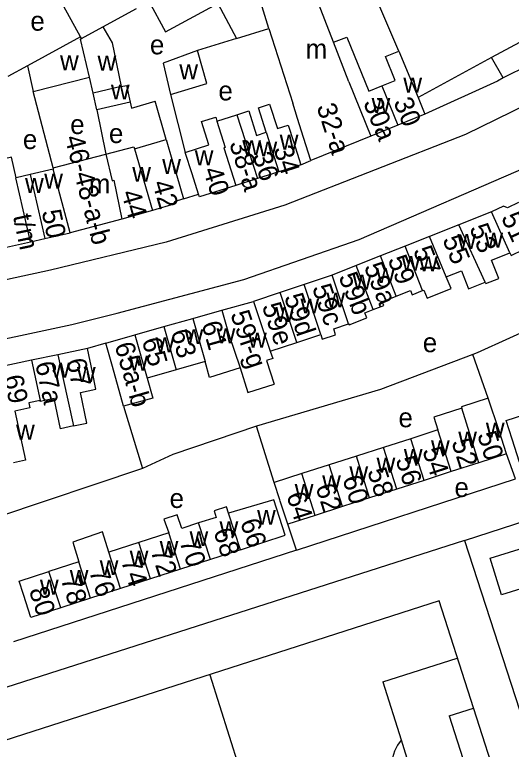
# Model space of a CAD drawing. Extents: x 157569 to 159501, y 382907 to 384670.
# Drawn here: x 159134.2 to 159236.8, y 383198.5 to 383350.2 of the extents above; entities that cross this region are included whole.
import ezdxf

# ---------------------------------------------------------------- set-up
doc = ezdxf.new("R2010")
doc.units = 0
for name, color, linetype in [('BLT_Basislijn', 7, 'Continuous'), ('BLT_Bebouwing', 7, 'Continuous'), ('BLT_Centroide', 7, 'Continuous'), ('BLT_Huisnummer', 7, 'Continuous'), ('BLT_Huisnummer_ tussenligend', 7, 'Continuous'), ('BLT_Huisnummer_reeks', 7, 'Continuous'), ('BLT_Onderdoorgang_en_onderverdeling', 7, 'Continuous'), ('BLT_Onderverdeling_panden', 7, 'Continuous')]:
    doc.layers.add(name, color=color, linetype=linetype)

msp = doc.modelspace()

# ---------------------------------------------------------------- linework, layer by layer
at = {"layer": 'BLT_Basislijn'}
for p, q in [((159262.09, 383350.88), (159235.12, 383337.11)), ((159180, 383345.26), (159171.98, 383342.81)), ((159235.12, 383337.11), (159232.71, 383341.31)), ((159136.86, 383339.6), (159132.8, 383337.38)), ((159166.38, 383333.67), (159169.45, 383321.74)), ((159165.51, 383324.4), (159163.22, 383332.29)), ((159151.19, 383330.54), (159153.01, 383321.36)), ((159193.32, 383319.19), (159195.37, 383320.06)), ((159169.08, 383312.13), (159172.19, 383313.1)), ((159153.02, 383282.36), (159149.23, 383281.25)), ((159232, 383270.96), (159228.83, 383279.98)), ((159156.72, 383269.31), (159160.58, 383256.46)), ((159187.8, 383253.56), (159184.15, 383265.21)), ((159237.62, 383254.3), (159235.8, 383259.46)), ((159160.58, 383256.46), (159126.18, 383244.9)), ((159192.4, 383239.63), (159237.62, 383254.3)), ((159192.4, 383239.63), (159190.6, 383244.94)), ((159227.11, 383241.57), (159118.79, 383206.87)), ((159192.4, 383239.63), (159133.97, 383220.64)), ((159210.21, 383212.39), (159225.62, 383217.27)), ((159174.52, 383213.85), (159181.45, 383191.99)), ((159210.21, 383212.39), (159214.01, 383200.41)), ((159223.95, 383205.38), (159228.94, 383206.96)), ((159223.95, 383205.38), (159228.04, 383192.5)), ((159214.01, 383200.4), (159222.38, 383174))]:
    msp.add_line(p, q, dxfattribs=at)
for points in [[(158983.24, 383235.61), (158982.98, 383236.31), (158981.28, 383239.26), (158981.31, 383241.77), (158983.04, 383243.59), (159007.41, 383254.28), (159036.07, 383262.73), (159100, 383276.35), (159146.03, 383286.21), (159155.39, 383288.52), (159181.52, 383295.52), (159205.36, 383303.77), (159241.92, 383319.57), (159301.34, 383349.43)], [(159258.99, 383340.92), (159227.33, 383325.46), (159190.02, 383310.81), (159165.47, 383303.18), (159141.61, 383297.45), (159119.64, 383292.64), (159100, 383288.81), (159051.92, 383279.92), (159027.35, 383274.07), (158997.57, 383264.08), (158986.46, 383259.17)], [(159235.12, 383337.11), (159233.89, 383336.44), (159218.91, 383329.63)], [(159142.14, 383318.53), (159138.07, 383334.3)], [(159158.09, 383332.11), (159158.37, 383330.89), (159163.22, 383332.29)], [(159243.1, 383286.39), (159229.71, 383280.36), (159228.83, 383279.98)], [(159228.83, 383279.98), (159209.75, 383272.75), (159184.15, 383265.21)], [(159227.11, 383241.57), (159314.29, 383269.88), (159323.12, 383265.83)], [(159184.15, 383265.21), (159166.87, 383259.35), (159160.58, 383256.46)], [(159227.11, 383241.57), (159242, 383195.83)], [(159214, 383200.39), (159213.28, 383199.32), (159212.68, 383198.1), (159212.23, 383196.73), (159211.98, 383195.26), (159211.96, 383193.71), (159212.19, 383192.15), (159212.67, 383190.64), (159213.38, 383189.23), (159214.29, 383187.98), (159215.35, 383186.92), (159216.5, 383186.06), (159217.7, 383185.41), (159218.9, 383184.96)]]:
    msp.add_lwpolyline(points, dxfattribs=at)
msp.add_lwpolyline([(159221.86, 383229.13), (159126.16, 383198.35), (159145.8, 383137.26), (159241.51, 383168.04)], close=True, dxfattribs=at)
at = {"layer": 'BLT_Bebouwing'}
for p, q in [((159213.51, 383342.64), (159200.32, 383373.83)), ((159200.04, 383344.48), (159190.74, 383368.68)), ((159255.71, 383353.81), (159232.71, 383341.31)), ((159152.4, 383347.65), (159159.35, 383351.46)), ((159180, 383345.26), (159186.71, 383347.31)), ((159186.71, 383347.31), (159191.64, 383331.91)), ((159147.8, 383345.57), (159136.86, 383339.6)), ((159171.98, 383342.81), (159164.85, 383340.15)), ((159173.93, 383335.93), (159171.98, 383342.81)), ((159164.85, 383340.15), (159166.38, 383333.67)), ((159232.71, 383341.31), (159217.54, 383333.06)), ((159136.86, 383339.6), (159138.07, 383334.3)), ((159138.07, 383334.3), (159149.65, 383337.3)), ((159150.4, 383333.99), (159149.65, 383337.3)), ((159156.2, 383335.32), (159157.31, 383335.57)), ((159157.31, 383335.57), (159158.09, 383332.11)), ((159166.38, 383333.67), (159173.93, 383335.93)), ((159151.19, 383330.54), (159150.4, 383333.99)), ((159217.54, 383333.06), (159218.91, 383329.63)), ((159158.09, 383332.11), (159151.19, 383330.54)), ((159175.99, 383328.2), (159180.08, 383329.5)), ((159218.91, 383329.63), (159213.36, 383327.37)), ((159213.36, 383327.37), (159207.78, 383325.11)), ((159207.78, 383325.11), (159195.37, 383320.06)), ((159142.14, 383318.53), (159153.01, 383321.36)), ((159193.32, 383319.19), (159188.76, 383317.74)), ((159142.14, 383318.53), (159142.2, 383318.27)), ((159188.76, 383317.74), (159184.34, 383316.34)), ((159184.34, 383316.34), (159179.89, 383314.93)), ((159162.65, 383309.77), (159156.34, 383307.94)), ((159232.66, 383309.45), (159225.95, 383306.79)), ((159225.95, 383306.79), (159219.9, 383304.39)), ((159137.5, 383303.29), (159140.46, 383303.97)), ((159140.46, 383303.97), (159145.65, 383305.16)), ((159219.9, 383304.39), (159214.84, 383302.38)), ((159128.14, 383301.18), (159137.5, 383303.29)), ((159214.84, 383302.38), (159209.79, 383300.37)), ((159209.79, 383300.37), (159204.71, 383298.36)), ((159204.71, 383298.36), (159199.79, 383296.4)), ((159199.79, 383296.4), (159193.98, 383294.46)), ((159193.98, 383294.46), (159189.05, 383292.81)), ((159189.05, 383292.81), (159183.55, 383290.97)), ((159177.03, 383289.17), (159183.55, 383290.97)), ((159171.03, 383287.47), (159177.03, 383289.17)), ((159165.03, 383285.77), (159171.03, 383287.47)), ((159159.03, 383284.07), (159165.03, 383285.77)), ((159153.02, 383282.36), (159159.03, 383284.07)), ((159187, 383280.68), (159192.49, 383282.51)), ((159149.23, 383281.25), (159143.13, 383279.96)), ((159143.13, 383279.96), (159137.71, 383278.81)), ((159137.71, 383278.81), (159129.52, 383277.08)), ((159173.56, 383278.55), (159167.56, 383276.85)), ((159167.56, 383276.85), (159161.55, 383275.15)), ((159221.62, 383264.42), (159216, 383262.61)), ((159216, 383262.61), (159210.39, 383260.81)), ((159210.39, 383260.81), (159204.77, 383259.01)), ((159204.77, 383259.01), (159199.15, 383257.21)), ((159235.8, 383259.46), (159230.08, 383257.62)), ((159199.15, 383257.21), (159193.53, 383255.4)), ((159230.08, 383257.62), (159224.38, 383255.81)), ((159193.53, 383255.4), (159187.8, 383253.56)), ((159224.38, 383255.81), (159218.76, 383254.01)), ((159218.76, 383254.01), (159213.14, 383252.22)), ((159213.14, 383252.22), (159207.52, 383250.42)), ((159201.91, 383248.61), (159196.3, 383246.79)), ((159196.3, 383246.79), (159190.6, 383244.94)), ((159166.03, 383243.2), (159159.84, 383241.2)), ((159159.84, 383241.2), (159153.66, 383239.2)), ((159180.83, 383239.7), (159174.64, 383237.7)), ((159147.48, 383237.19), (159141.29, 383235.19)), ((159174.64, 383237.7), (159168.46, 383235.69)), ((159168.46, 383235.69), (159162.27, 383233.69)), ((159162.27, 383233.69), (159156.09, 383231.69)), ((159156.09, 383231.69), (159149.91, 383229.68)), ((159149.91, 383229.68), (159143.73, 383227.68))]:
    msp.add_line(p, q, dxfattribs=at)
for points in [[(159147.8, 383345.57), (159131.42, 383375.48), (159129.2, 383379.53)], [(159161.82, 383353.07), (159165.38, 383346.61), (159176.15, 383352.51), (159180, 383345.26)], [(159152.4, 383347.65), (159154.32, 383344.35), (159156.2, 383335.32)], [(159200.04, 383344.48), (159202.79, 383345.53), (159207.32, 383334.38), (159210.06, 383335.49)], [(159210.06, 383335.49), (159212.79, 383336.6), (159210.79, 383341.53), (159213.51, 383342.64)], [(159186.18, 383325.88), (159184.57, 383330.95), (159186.87, 383331.68), (159188.46, 383326.66), (159190.71, 383327.39), (159191.81, 383323.96), (159193.32, 383319.19)], [(159195.37, 383320.06), (159193.85, 383324.83), (159192.6, 383328.76), (159191.64, 383331.91)], [(159180.08, 383329.5), (159182.56, 383330.29), (159184.16, 383325.24), (159186.18, 383325.88)], [(159169.45, 383321.74), (159174.34, 383323.29), (159172.82, 383328.09), (159175.75, 383329.03), (159175.99, 383328.2)], [(159158.95, 383322.49), (159162.5, 383323.52), (159165.51, 383324.4)], [(159165.51, 383324.4), (159166.83, 383319.88), (159167.69, 383316.93), (159169.08, 383312.13)], [(159153.01, 383321.36), (159158.84, 383322.89), (159158.95, 383322.49)], [(159134.54, 383316.5), (159133.56, 383320.73), (159130.86, 383320.12), (159131.82, 383315.88), (159125.38, 383314.4)], [(159172.19, 383313.1), (159170.85, 383317.31), (159169.45, 383321.74)], [(159142.2, 383318.27), (159137.41, 383317.16)], [(159145.65, 383305.16), (159142.2, 383318.27)], [(159137.41, 383317.16), (159134.54, 383316.5)], [(159179.89, 383314.93), (159172.37, 383312.55), (159172.19, 383313.1)], [(159169.08, 383312.13), (159167.14, 383311.56), (159167.27, 383311.11), (159162.65, 383309.77)], [(159238.23, 383311.37), (159236.01, 383310.32), (159235.14, 383310.63), (159232.66, 383309.45)], [(159156.34, 383307.94), (159145.65, 383305.16)], [(159231.39, 383294.93), (159231.53, 383294.63), (159234.2, 383295.7), (159232.69, 383299.47), (159234.59, 383300.23), (159236.49, 383300.99)], [(159236.49, 383300.99), (159236.74, 383300.44), (159239.27, 383301.68), (159240.47, 383299.26), (159243.32, 383300.66)], [(159223.33, 383296.04), (159226.45, 383297.28), (159227.94, 383293.55), (159231.39, 383294.93)], [(159218.42, 383293.19), (159218.71, 383293.3), (159219.38, 383291.63), (159224.33, 383293.6), (159223.33, 383296.04)], [(159212.99, 383292.03), (159215.96, 383293.21), (159216.31, 383292.35), (159218.42, 383293.19)], [(159208.27, 383289.29), (159210.42, 383290.15), (159210.12, 383290.89), (159212.99, 383292.03)], [(159203.18, 383286.33), (159203.29, 383286.12), (159206.96, 383287.58), (159206.55, 383288.61), (159208.27, 383289.29)], [(159197.42, 383284.16), (159197.73, 383283.14), (159200.5, 383284.07), (159200.11, 383285.3), (159203.18, 383286.33)], [(159192.49, 383282.51), (159197.42, 383284.16)], [(159146.39, 383265.24), (159149.12, 383265.82), (159147.78, 383272.16), (159151.01, 383272.84), (159150.27, 383276.36), (159149.23, 383281.25)], [(159156.72, 383269.31), (159154.39, 383277.54), (159153.02, 383282.36)], [(159187, 383280.68), (159187.51, 383279.16), (159186.24, 383278.76), (159187.77, 383273.89)], [(159180.78, 383277.28), (159174.45, 383275.28), (159173.56, 383278.55)], [(159180.78, 383277.28), (159182.39, 383272.19), (159187.77, 383273.89)], [(159161.55, 383275.15), (159162.72, 383271.01), (159156.72, 383269.31)], [(159139.46, 383270.49), (159137.16, 383270), (159137.38, 383268.97), (159134.26, 383268.3), (159136.43, 383258.16), (159133.99, 383257.64)], [(159146.39, 383265.24), (159143.68, 383264.67), (159142.37, 383270.92), (159139.5, 383270.32), (159139.46, 383270.49)], [(159232, 383270.96), (159226.45, 383269.23), (159226.54, 383268.92)], [(159235.8, 383259.46), (159234.27, 383264.22), (159232, 383270.96)], [(159226.54, 383268.92), (159220.78, 383267.07), (159221.62, 383264.42)], [(159244.24, 383259.65), (159238.47, 383257.79), (159236.93, 383262.55), (159235.73, 383266.37), (159241.46, 383268.23)], [(159190.6, 383244.94), (159189.06, 383249.7), (159188.96, 383250), (159187.8, 383253.56)], [(159180.83, 383239.7), (159190.07, 383242.7), (159187.71, 383250), (159178.39, 383247.21)], [(159207.52, 383250.42), (159206.21, 383250), (159201.91, 383248.61)], [(159178.39, 383247.21), (159177.95, 383248.54), (159175.39, 383247.69), (159175.81, 383246.37), (159172.21, 383245.21)], [(159172.21, 383245.21), (159168.75, 383244.09), (159167.77, 383246.92), (159165.02, 383245.97), (159166.03, 383243.2)], [(159153.66, 383239.2), (159152.35, 383243.35), (159146.24, 383241.26), (159147.48, 383237.19)], [(159232.37, 383237.93), (159243.27, 383241.29), (159245.6, 383233.72), (159234.71, 383230.36), (159232.37, 383237.93)], [(159143.73, 383227.68), (159137.58, 383225.69), (159136.04, 383230.45), (159135.15, 383233.2), (159141.29, 383235.19)]]:
    msp.add_lwpolyline(points, dxfattribs=at)
at = {"layer": 'BLT_Onderdoorgang_en_onderverdeling'}
msp.add_line((159137.41, 383317.16), (159140.46, 383303.97), dxfattribs=at)
msp.add_lwpolyline([(159137.5, 383303.29), (159134.45, 383316.48), (159134.54, 383316.5)], dxfattribs=at)
at = {"layer": 'BLT_Onderverdeling_panden'}
for p, q in [((159147.99, 383345.23), (159152.4, 383347.65)), ((159147.99, 383345.23), (159147.8, 383345.57)), ((159203.23, 383336.31), (159200.04, 383344.48)), ((159213.51, 383342.64), (159217.54, 383333.06)), ((159203.23, 383336.31), (159207.78, 383325.11)), ((159156.2, 383335.32), (159150.4, 383333.99)), ((159210.06, 383335.49), (159213.36, 383327.37)), ((159180.08, 383329.5), (159184.34, 383316.34)), ((159186.18, 383325.88), (159188.76, 383317.74)), ((159158.95, 383322.49), (159162.65, 383309.77)), ((159236.49, 383300.99), (159232.66, 383309.45)), ((159231.39, 383294.93), (159225.95, 383306.79)), ((159223.33, 383296.04), (159219.9, 383304.39)), ((159218.42, 383293.19), (159214.84, 383302.38)), ((159212.99, 383292.03), (159209.79, 383300.37)), ((159208.27, 383289.29), (159204.71, 383298.36)), ((159203.18, 383286.33), (159199.79, 383296.4)), ((159197.42, 383284.16), (159193.98, 383294.46)), ((159192.49, 383282.51), (159189.05, 383292.81)), ((159171.03, 383287.47), (159173.56, 383278.55)), ((159165.03, 383285.77), (159167.56, 383276.85)), ((159159.03, 383284.07), (159161.55, 383275.15)), ((159143.13, 383279.96), (159146.39, 383265.24)), ((159137.71, 383278.81), (159139.46, 383270.49)), ((159230.08, 383257.62), (159226.54, 383268.92)), ((159224.38, 383255.81), (159221.62, 383264.42)), ((159218.76, 383254.01), (159216, 383262.61)), ((159213.14, 383252.22), (159210.39, 383260.81)), ((159207.52, 383250.42), (159204.77, 383259.01)), ((159201.91, 383248.61), (159199.15, 383257.21)), ((159196.3, 383246.79), (159193.53, 383255.4)), ((159180.83, 383239.7), (159178.39, 383247.21)), ((159174.64, 383237.7), (159172.21, 383245.21)), ((159168.46, 383235.69), (159166.03, 383243.2)), ((159162.27, 383233.69), (159159.84, 383241.2)), ((159156.09, 383231.69), (159153.66, 383239.2)), ((159149.91, 383229.68), (159147.48, 383237.19)), ((159143.73, 383227.68), (159141.29, 383235.19))]:
    msp.add_line(p, q, dxfattribs=at)
for points in [[(159186.71, 383347.31), (159183.44, 383357.9), (159181.63, 383363.77)], [(159149.65, 383337.3), (159147.82, 383345.14), (159147.99, 383345.23)], [(159175.99, 383328.2), (159177.71, 383322.78), (159177.42, 383322.69), (159179.89, 383314.93)], [(159153.01, 383321.36), (159154.37, 383315.88), (159154.71, 383315.98), (159156.34, 383307.94)], [(159183.55, 383290.97), (159185.14, 383286.23), (159187, 383280.68)], [(159177.03, 383289.17), (159178.39, 383284.36), (159180.78, 383277.28)]]:
    msp.add_lwpolyline(points, dxfattribs=at)

# ---------------------------------------------------------------- texts
at = {"layer": 'BLT_Centroide'}
for s, p in [('e', (159137.46, 383346.87)), ('e', (159162.15, 383341.98)), ('m', (159194.3, 383341.12)), ('w', (159143.59, 383338.7)), ('w', (159151.33, 383338.63)), ('w', (159168.22, 383336.84)), ('w', (159214.48, 383334.09)), ('w', (159154.09, 383332.66)), ('e', (159176.29, 383332.47)), ('w', (159207.92, 383329.89)), ('e', (159145.69, 383325.52)), ('e', (159153.69, 383323.67)), ('e', (159135.92, 383322.43)), ('w', (159188.95, 383322.31)), ('w', (159181.22, 383321.17)), ('w', (159184.58, 383320.91)), ('w', (159171.4, 383319.09)), ('w', (159164.69, 383317.27)), ('w', (159140.32, 383314.27)), ('w', (159158.5, 383315.67)), ('w', (159136.36, 383313.36)), ('m', (159149.53, 383313.25)), ('w', (159225.64, 383301.81)), ('w', (159231.22, 383302.09)), ('w', (159214.11, 383297.28)), ('w', (159217.71, 383297.19)), ('w', (159208.86, 383294.77)), ('w', (159204.03, 383293.39)), ('w', (159193.23, 383288.48)), ('w', (159198.58, 383289.72)), ('w', (159188.02, 383286.73)), ('w', (159169.3, 383282.16)), ('w', (159175.91, 383282.3)), ('w', (159182.41, 383281.42)), ('w', (159163.3, 383280.45)), ('e', (159218.49, 383280.48)), ('w', (159157.88, 383276.69)), ('w', (159141.78, 383275.25)), ('w', (159147.08, 383274.34)), ('e', (159213.47, 383264.98)), ('w', (159231.52, 383262.84)), ('w', (159134.5, 383262.41)), ('w', (159225.81, 383261.02)), ('w', (159220.19, 383259.22)), ('w', (159214.58, 383257.42)), ('w', (159208.95, 383255.61)), ('w', (159203.34, 383253.81)), ('w', (159197.72, 383252)), ('e', (159225.03, 383250.58)), ('w', (159192.05, 383250.17)), ('e', (159166.21, 383248.31)), ('w', (159184.27, 383244.84)), ('w', (159176.52, 383242.45)), ('w', (159170.33, 383240.45)), ('w', (159164.16, 383238.45)), ('w', (159157.97, 383236.44)), ('w', (159151.78, 383234.44)), ('w', (159145.59, 383232.44)), ('w', (159139.44, 383230.44))]:
    msp.add_text(s, height=4, dxfattribs=at).set_placement(p)
at = {"layer": 'BLT_Huisnummer'}
for s, rotation, p in [('30', 292.1257, (159212.37, 383332.17)), ('34', 287.603, (159187.63, 383322.48)), ('40', 287.6015, (159173.08, 383318.08)), ('42', 286.1879, (159162.61, 383315.42)), ('53', 291.5822, (159228.07, 383306.14)), ('59', 291.5822, (159211.2, 383299.61)), ('59a', 291.5822, (159206.29, 383298.14)), ('59b', 291.5822, (159201.04, 383296.08)), ('59c', 288.5325, (159195.6, 383293.83)), ('59d', 288.5256, (159189.82, 383291.91)), ('59e', 288.5255, (159185.23, 383290.01)), ('61', 285.8282, (159172.77, 383286.34)), ('63', 285.8206, (159166.41, 383284.66)), ('65', 285.8163, (159160.44, 383282.94)), ('67a', 281.9564, (159138.45, 383278.18)), ('67', 281.9526, (159144.9, 383278.82)), ('69', 282.1012, (159131.93, 383275.39)), ('50', 287.7961, (159229.69, 383263.45)), ('54', 287.7976, (159218.37, 383260.22)), ('58', 287.7982, (159206.99, 383255.92)), ('64', 287.798, (159190.27, 383250.97)), ('66', 287.9438, (159180.74, 383245.43)), ('70', 287.946, (159168.21, 383241.4)), ('74', 287.946, (159156.14, 383237.4)), ('78', 287.946, (159143.67, 383233.63)), ('80', 287.9494, (159137.13, 383231.34))]:
    msp.add_text(s, height=4, rotation=rotation, dxfattribs=at).set_placement(p)
at = {"layer": 'BLT_Huisnummer_ tussenligend'}
for s, rotation, p in [('30a', 292.127, (159206.13, 383332.04)), ('36', 287.603, (159183.29, 383321.14)), ('44', 286.1879, (159156.18, 383313.41)), ('51', 294.513, (159234.6, 383308.32)), ('55', 291.5822, (159222.5, 383303.8)), ('57', 291.5822, (159216.43, 383301.51)), ('52', 287.7961, (159224.37, 383261.95)), ('56', 287.7976, (159212.83, 383258.3)), ('60', 287.7982, (159201.84, 383254.39)), ('62', 287.7982, (159196.3, 383252.67)), ('68', 287.9438, (159175.21, 383243.5)), ('72', 287.946, (159162.25, 383239.46)), ('76', 287.946, (159149.54, 383235.27))]:
    msp.add_text(s, height=4, rotation=rotation, dxfattribs=at).set_placement(p)
at = {"layer": 'BLT_Huisnummer_reeks'}
for s, rotation, p in [('32-a', 287.694, (159196.53, 383331.2)), ('46-48-a-b', 284.6421, (159144.52, 383324.78)), ('38-a', 287.603, (159178.49, 383323.63)), ('50', 281.8071, (159139.78, 383309.54)), ('t/m', 281.8071, (159133.85, 383308.6)), ('59f-g', 288.5255, (159178.72, 383288.38)), ('65a-b', 285.8176, (159154.82, 383281.97))]:
    msp.add_text(s, height=4, rotation=rotation, dxfattribs=at).set_placement(p)

doc.saveas('drawing.dxf')
